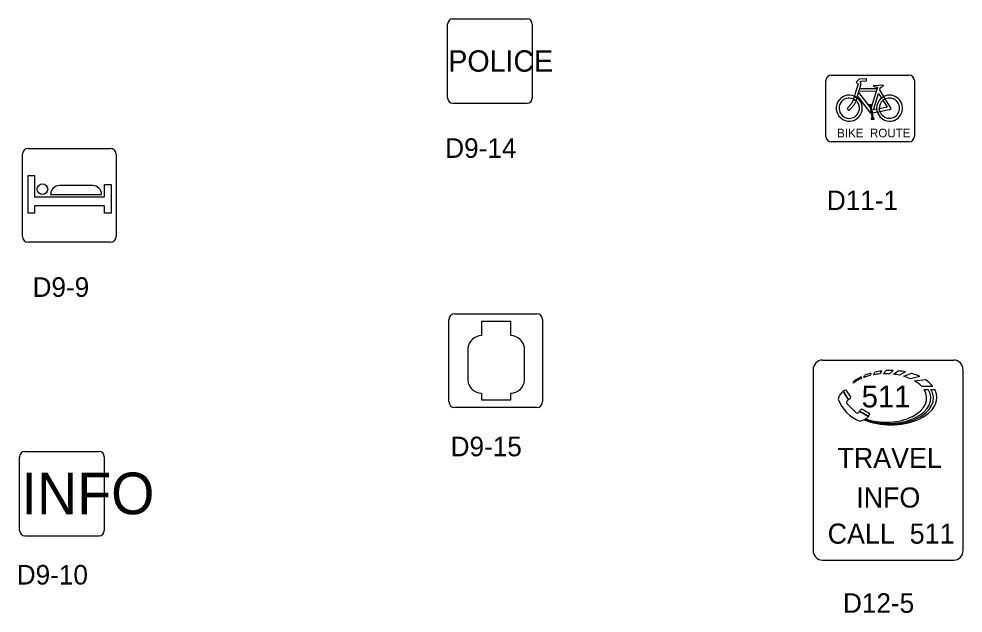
# Model space of a CAD drawing. Extents: x 42133 to 45533, y 41351 to 47951.
# Drawn here: x 42525.9 to 42888.2, y 47190.2 to 47418 of the extents above; entities that cross this region are included whole.
import ezdxf

# ---------------------------------------------------------------- set-up
doc = ezdxf.new("R2010")
doc.units = 0
doc.layers.add('P_TRAF_SIGN_SignDetails', color=7, linetype='Continuous')

msp = doc.modelspace()

# ---------------------------------------------------------------- linework, layer by layer
at = {"layer": 'P_TRAF_SIGN_SignDetails'}
for p, q in [((42690.42, 47387.7), (42690.42, 47415.99)), ((42692.46, 47418.02), (42720.9, 47418.02)), ((42722.94, 47415.99), (42722.94, 47387.65)), ((42835.54, 47372.91), (42835.54, 47394.39)), ((42837.59, 47396.43), (42867.47, 47396.43)), ((42848.38, 47394.92), (42847.25, 47393.74)), ((42851.12, 47395.07), (42848.38, 47394.92)), ((42849.12, 47394.1), (42851.18, 47394.22)), ((42851.18, 47394.22), (42851.12, 47395.07)), ((42869.53, 47394.39), (42869.53, 47372.91)), ((42847.91, 47392.96), (42846.97, 47389.92)), ((42847.25, 47393.74), (42847.91, 47392.96)), ((42848.21, 47390.26), (42848.55, 47391.34)), ((42848.21, 47390.26), (42848.55, 47391.34)), ((42848.55, 47391.34), (42849.12, 47393.21)), ((42848.55, 47391.34), (42855.2, 47391.31)), ((42848.73, 47393.68), (42849.12, 47394.1)), ((42849.12, 47393.21), (42848.73, 47393.68)), ((42853.81, 47392.41), (42853.78, 47392.24)), ((42857.63, 47392.61), (42853.81, 47392.41)), ((42855.2, 47391.31), (42854.88, 47390.22)), ((42855.2, 47391.31), (42854.88, 47390.22)), ((42855.32, 47391.79), (42855.2, 47391.31)), ((42856.21, 47390.85), (42856.47, 47391.84)), ((42857.86, 47388.2), (42856.21, 47390.85)), ((42857.69, 47392.5), (42857.63, 47392.61)), ((42846.07, 47386.69), (42846.23, 47387.23)), ((42846.22, 47387.26), (42846.54, 47388.36)), ((42846.23, 47387.23), (42847.19, 47386.6)), ((42846.97, 47389.91), (42846.54, 47388.36)), ((42846.54, 47388.36), (42847.51, 47387.8)), ((42847.51, 47387.8), (42847.19, 47386.6)), ((42847.51, 47387.8), (42847.73, 47388.56)), ((42847.73, 47388.56), (42848.1, 47389.86)), ((42847.73, 47388.56), (42848.1, 47389.86)), ((42852.86, 47381.84), (42847.73, 47388.56)), ((42848.1, 47389.86), (42848.21, 47390.26)), ((42848.1, 47389.86), (42852.56, 47384.04)), ((42854.88, 47390.22), (42848.21, 47390.26)), ((42854.88, 47390.22), (42852.99, 47384)), ((42853.88, 47383.15), (42855.79, 47389.44)), ((42855.79, 47389.44), (42856.92, 47387.63)), ((42856.92, 47387.63), (42857.86, 47388.2)), ((42858.37, 47387.36), (42857.44, 47386.8)), ((42858.37, 47387.36), (42857.82, 47388.26)), ((42860.28, 47384.29), (42858.37, 47387.37)), ((42692.46, 47385.68), (42720.9, 47385.68)), ((42844.14, 47384.12), (42845.69, 47385.82)), ((42846.6, 47385.2), (42844.94, 47383.37)), ((42847.17, 47386.6), (42847.08, 47386.28)), ((42853.18, 47385.13), (42852, 47385.13)), ((42852, 47385.13), (42852, 47384.89)), ((42852, 47384.89), (42852.39, 47384.89)), ((42852.39, 47384.89), (42852.56, 47384.04)), ((42852.56, 47384.04), (42852.96, 47381.85)), ((42852.56, 47384.04), (42852.96, 47381.85)), ((42852.99, 47384), (42852.82, 47384.89)), ((42852.82, 47384.89), (42853.18, 47384.89)), ((42852.99, 47384), (42853.41, 47381.94)), ((42853.41, 47381.94), (42852.99, 47384)), ((42853.18, 47384.89), (42853.18, 47385.13)), ((42855.04, 47383.39), (42853.88, 47383.15)), ((42855.27, 47382.32), (42855.07, 47383.39)), ((42859.06, 47384.19), (42856.04, 47383.59)), ((42856.04, 47383.59), (42856.27, 47382.51)), ((42857.44, 47386.8), (42859.06, 47384.19)), ((42852.96, 47381.85), (42852.86, 47381.84)), ((42852.96, 47381.85), (42853.35, 47379.8)), ((42853.35, 47379.8), (42853, 47379.8)), ((42853, 47379.8), (42853, 47379.6)), ((42853.41, 47381.94), (42855.27, 47382.32)), ((42853.82, 47379.81), (42853.41, 47381.94)), ((42854.16, 47379.81), (42853.82, 47379.81)), ((42854.16, 47379.6), (42854.16, 47379.81)), ((42855.28, 47382.28), (42856.27, 47382.52)), ((42856.27, 47382.51), (42859.81, 47383.22)), ((42853, 47379.6), (42854.16, 47379.6)), ((42867.47, 47370.86), (42837.59, 47370.86)), ((42527.3, 47334.61), (42527.3, 47366.1)), ((42529.55, 47368.34), (42561.03, 47368.34)), ((42563.28, 47366.1), (42563.28, 47334.61)), ((42561.03, 47332.36), (42529.55, 47332.36)), ((42693.18, 47304.98), (42724.66, 47304.98)), ((42690.93, 47271.25), (42690.93, 47302.74)), ((42726.9, 47302.74), (42726.9, 47271.25)), ((42834.27, 47287.22), (42884.63, 47287.22)), ((42830.67, 47283.38), (42830.67, 47214.3)), ((42852.85, 47282.13), (42852.54, 47281.28)), ((42853.82, 47281.55), (42854.32, 47282.53)), ((42856.97, 47282.98), (42856.23, 47281.88)), ((42857.61, 47281.95), (42858.66, 47283.15)), ((42861.39, 47283.18), (42860, 47281.93)), ((42861.52, 47281.78), (42863.35, 47283.06)), ((42866.12, 47282.66), (42863.78, 47281.41)), ((42865.43, 47280.99), (42868.37, 47282.12)), ((42888.23, 47214.3), (42888.23, 47283.38)), ((42846.15, 47278.38), (42846.15, 47278.8)), ((42849.14, 47280.73), (42849.08, 47280.1)), ((42850.19, 47280.55), (42850.36, 47281.29)), ((42871.61, 47280.9), (42868.09, 47280.02)), ((42869.62, 47279.2), (42873.76, 47279.7)), ((42842.19, 47275.3), (42844.3, 47271.99)), ((42844.3, 47271.98), (42842.22, 47275.3)), ((42876.61, 47277.08), (42872.33, 47277.08)), ((42873.23, 47275.92), (42874.88, 47275.92)), ((42875.9, 47275.92), (42877.35, 47275.92)), ((42844.96, 47272.44), (42844.3, 47271.98)), ((42845.36, 47273.25), (42845.36, 47273.26)), ((42724.66, 47269.01), (42693.18, 47269.01)), ((42843.63, 47270.5), (42847.1, 47267.07)), ((42848.52, 47267.63), (42848.84, 47267.99)), ((42848.52, 47267.63), (42851.95, 47265.61)), ((42851.96, 47265.63), (42848.52, 47267.63)), ((42848.84, 47267.99), (42849.06, 47268.26)), ((42850.33, 47264.36), (42850.23, 47264.3)), ((42850.5, 47264.46), (42850.78, 47264.62)), ((42526.21, 47221.84), (42526.21, 47250.13)), ((42528.24, 47252.16), (42556.69, 47252.16)), ((42558.72, 47250.13), (42558.72, 47221.79)), ((42528.24, 47219.82), (42556.69, 47219.82)), ((42834.27, 47210.46), (42884.63, 47210.46))]:
    msp.add_line(p, q, dxfattribs=at)
for points in [[(42846.54, 47388.36), (42846.22, 47387.26), (42846.23, 47387.23), (42847.19, 47386.6), (42847.51, 47387.8)], [(42558.79, 47346.32), (42531.99, 47346.32), (42531.99, 47343.51), (42529.45, 47343.51), (42529.45, 47357.91), (42531.99, 47357.91), (42531.99, 47349.82), (42558.79, 47349.82), (42558.79, 47354.48), (42561.33, 47354.48), (42561.33, 47343.51), (42558.79, 47343.51)], [(42558.79, 47346.32), (42531.99, 47346.32), (42531.99, 47343.51), (42529.45, 47343.51), (42529.45, 47357.91), (42531.99, 47357.91), (42531.99, 47349.82), (42558.79, 47349.82), (42558.79, 47354.48), (42561.33, 47354.48), (42561.33, 47343.51), (42558.79, 47343.51)], [(42558.79, 47346.32), (42531.99, 47346.32), (42531.99, 47343.51), (42529.45, 47343.51), (42529.45, 47357.91), (42531.99, 47357.91), (42531.99, 47349.82), (42558.79, 47349.82), (42558.79, 47354.48), (42561.33, 47354.48), (42561.33, 47343.51), (42558.79, 47343.51)]]:
    msp.add_lwpolyline(points, close=True, dxfattribs=at)
for points in [[(42857.44, 47386.8), (42858.37, 47387.36), (42857.81, 47388.3), (42856.92, 47387.63), (42856.88, 47387.65)], [(42855.04, 47383.39), (42855.28, 47382.28), (42856.27, 47382.52), (42856.06, 47383.57)], [(42538.09, 47350.71), (42557.7, 47350.71)], [(42538.09, 47350.71), (42557.7, 47350.71)], [(42538.09, 47350.71), (42557.7, 47350.71)], [(42554.2, 47354.15), (42541.58, 47354.15)], [(42554.2, 47354.15), (42541.58, 47354.15)], [(42554.2, 47354.15), (42541.58, 47354.15)], [(42714.67, 47296.56), (42714.67, 47301.99), (42703.48, 47301.99), (42703.48, 47296.56)], [(42714.67, 47296.56), (42714.67, 47301.99), (42703.48, 47301.99), (42703.48, 47296.56)], [(42714.67, 47296.56), (42714.67, 47301.99), (42703.48, 47301.99), (42703.48, 47296.56)], [(42698.2, 47291.57), (42698.2, 47279.48)], [(42698.2, 47291.57), (42698.2, 47279.48)], [(42698.2, 47291.57), (42698.2, 47279.48)], [(42719.95, 47279.48), (42719.95, 47291.57)], [(42719.95, 47279.48), (42719.95, 47291.57)], [(42719.95, 47279.48), (42719.95, 47291.57)], [(42703.48, 47274.46), (42703.48, 47271.99), (42714.67, 47271.99), (42714.67, 47274.46)], [(42703.48, 47274.46), (42703.48, 47271.99), (42714.67, 47271.99), (42714.67, 47274.46)], [(42703.48, 47274.46), (42703.48, 47271.99), (42714.67, 47271.99), (42714.67, 47274.46)]]:
    msp.add_lwpolyline(points, dxfattribs=at)
msp.add_circle((42534.97, 47352.73), 2.02, dxfattribs=at)
msp.add_circle((42534.97, 47352.73), 2.02, dxfattribs=at)
msp.add_circle((42534.97, 47352.73), 2.02, dxfattribs=at)
for centre, radius, start, end in [((42692.46, 47415.99), 2.03, 90, 180), ((42720.9, 47415.99), 2.03, 0, 90), ((42837.59, 47394.38), 2.05, 90, 180), ((42867.47, 47394.38), 2.05, 360, 90), ((42856.3, 47397.95), 6.24, 246.229, 261.1184), ((42856.55, 47393.17), 1.32, 266.6391, 329.7311), ((42857.61, 47392.53), 0.0862, 336.8194, 78.5167), ((42692.46, 47387.71), 2.03, 180, 270), ((42720.9, 47387.71), 2.03, 270, 0), ((42844.54, 47383.8), 4.99, 66.4023, 53.4605), ((42844.54, 47383.75), 3.89, 64.4104, 47.1387), ((42860.03, 47383.79), 4.98, 129.2526, 184.6549), ((42860.03, 47383.79), 4.98, 197.6727, 116.3307), ((42859.94, 47383.8), 3.89, 199.3058, 113.7924), ((42844.43, 47383.63), 0.559, 122.8763, 330.7719), ((42824.93, 47395.52), 22.91, 334.9582, 337.3217), ((42825.94, 47395.11), 22.91, 334.4184, 337.3217), ((42859.94, 47383.8), 3.89, 129.8696, 183.4253), ((42859.94, 47383.8), 0.595, 257.4123, 57.0678), ((42837.59, 47372.91), 2.05, 180, 270), ((42867.47, 47372.91), 2.05, 270, 0), ((42529.54, 47366.09), 2.24, 90, 180), ((42561.03, 47366.09), 2.24, 0, 90), ((42541.58, 47350.65), 3.49, 90, 179.0898), ((42541.58, 47350.65), 3.49, 90, 179.0898), ((42541.58, 47350.65), 3.49, 90, 179.0898), ((42554.2, 47350.65), 3.49, 0.9102, 90), ((42554.2, 47350.65), 3.49, 0.9102, 90), ((42554.2, 47350.65), 3.49, 0.9102, 90), ((42529.54, 47334.61), 2.24, 180, 270), ((42561.03, 47334.61), 2.24, 270, 0), ((42693.17, 47302.74), 2.24, 90, 180), ((42724.66, 47302.74), 2.24, 0, 90), ((42703.63, 47291.11), 5.45, 91.6261, 175.146), ((42703.63, 47291.11), 5.45, 91.6261, 175.146), ((42703.63, 47291.11), 5.45, 91.6261, 175.146), ((42714.52, 47291.12), 5.44, 4.7665, 88.4625), ((42714.52, 47291.12), 5.44, 4.7665, 88.4625), ((42714.52, 47291.12), 5.44, 4.7665, 88.4625), ((42703.62, 47279.89), 5.43, 184.3697, 268.5281), ((42703.62, 47279.89), 5.43, 184.3697, 268.5281), ((42703.62, 47279.89), 5.43, 184.3697, 268.5281), ((42714.54, 47279.89), 5.42, 271.3838, 355.7173), ((42714.54, 47279.89), 5.42, 271.3838, 355.7173), ((42714.54, 47279.89), 5.42, 271.3838, 355.7173), ((42846.04, 47270.77), 5.94, 130.4347, 166.1646), ((42843.67, 47272.86), 2.84, 99.7023, 120.7921), ((42843.2, 47275.45), 0.207, 35.2868, 92.2905), ((42911.85, 47317.52), 80.3, 211.4914, 213.7269), ((42693.17, 47271.25), 2.24, 180, 270), ((42724.66, 47271.25), 2.24, 270, 0), ((42853.98, 47277.31), 14.63, 200.4595, 248.4044), ((42844.78, 47270.78), 1.31, 111.8435, 174.5089), ((42844.65, 47272.76), 0.445, 313.7884, 22.7385), ((42844.02, 47270.87), 0.537, 176.1892, 224.7155), ((42847.54, 47267.93), 1.03, 278.8261, 343.0748), ((42849.33, 47268.03), 0.355, 81.1672, 138.3265), ((42769.69, 47132.13), 157.84, 58.4772, 59.6765), ((42847.59, 47267.7), 0.797, 232.551, 277.7015), ((42847.1, 47270.27), 6.73, 282.8575, 316.22), ((42848.04, 47267.85), 4.5, 330.4326, 341.7852), ((42852.12, 47266.5), 0.205, 345.5779, 61.1463), ((42528.24, 47250.13), 2.03, 90, 180), ((42556.69, 47250.13), 2.03, 0, 90), ((42528.24, 47221.85), 2.03, 180, 270), ((42556.69, 47221.85), 2.03, 270, 0)]:
    msp.add_arc(centre, radius, start, end, dxfattribs=at)
for centre, major_axis, ratio, start_param, end_param in [((42834.27, 47283.38), (0, -3.84), 0.937267, 3.141593, 4.712389), ((42884.63, 47283.38), (0, 3.84), 0.937267, 4.712389, 6.283185), ((42860.38, 47272.71), (17.64, 0.02), 0.591216, 2.011433, 2.174131), ((42858.66, 47272.69), (15.68, -0.08), 0.593139, 1.729205, 1.887612), ((42860.51, 47272.77), (17.64, 0.02), 0.591216, 1.771674, 1.928512), ((42858.7, 47272.66), (15.68, -0.08), 0.593139, 1.491014, 1.643258), ((42860.4, 47272.77), (17.64, 0.02), 0.591216, 1.513986, 1.669268), ((42860.52, 47272.77), (17.64, 0.02), 0.591216, 1.246703, 1.408649), ((42860.55, 47272.76), (17.64, 0.02), 0.591216, 0.89287, 1.111146), ((42860.53, 47272.77), (17.64, 0.02), 0.591216, 2.272046, 2.523507), ((42858.57, 47272.67), (15.68, -0.08), 0.593139, 2.224537, 2.488567), ((42858.68, 47272.71), (15.68, -0.08), 0.593139, 1.976929, 2.146282), ((42858.57, 47272.66), (15.68, -0.08), 0.593139, 1.235313, 1.384361), ((42858.64, 47272.63), (15.68, -0.08), 0.593139, 0.926698, 1.125462), ((42858.64, 47272.59), (15.68, -0.08), 0.593139, 0.51226, 0.798503), ((42860.49, 47272.82), (17.64, 0.02), 0.591216, 0.417997, 0.718368), ((42860.53, 47272.77), (17.64, 0.02), 0.591216, 4.087972, 6.587753), ((42859.87, 47272.66), (16.98, -0.09), 0.593139, 4.11911, 6.621761), ((42859.37, 47272.66), (16.48, -0.09), 0.593139, 4.146763, 6.631863), ((42858.57, 47272.67), (15.68, -0.08), 0.593139, 4.19513, 6.649471), ((42834.27, 47214.3), (0, -3.84), 0.937267, 4.712389, 6.283185), ((42884.63, 47214.3), (0, 3.84), 0.937267, 3.141593, 4.712389)]:
    msp.add_ellipse(centre, major_axis=major_axis, ratio=ratio, start_param=start_param, end_param=end_param, dxfattribs=at)

# ---------------------------------------------------------------- texts
for s, height, p in [('POLICE', 8.199, (42690.71, 47397.77)), ('BIKE  ROUTE', 3.3251, (42839.88, 47372.6)), ('D9-14', 7.5, (42689.53, 47364.74)), ('D11-1', 7.5, (42835.94, 47344.69)), ('D9-9', 7.5, (42531.2, 47311.43)), ('511', 8.4, (42849.3, 47269.01)), ('D9-15', 7.5, (42691.6, 47250.31)), ('TRAVEL', 7.703, (42840, 47245.82)), ('INFO', 15.971, (42526.94, 47228.08)), ('INFO', 7.703, (42847.2, 47230.64)), ('CALL  511', 7.703, (42836.25, 47216.79)), ('D9-10', 7.5, (42525.12, 47201.13)), ('D12-5', 7.5, (42842.13, 47190.27))]:
    msp.add_text(s, height=height, dxfattribs=at).set_placement(p)

doc.saveas('drawing.dxf')
